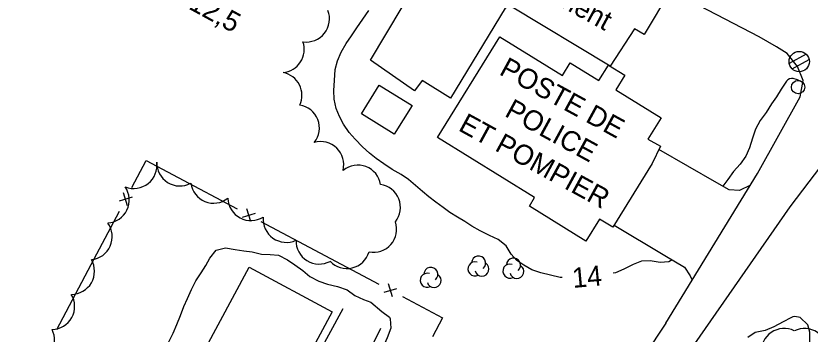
# Model space of a CAD drawing. Extents: x 219136 to 222520, y 5421589 to 5424530.
# Drawn here: x 220257.1 to 220376, y 5423476.2 to 5423523.8 of the extents above; entities that cross this region are included whole.
import ezdxf

# ---------------------------------------------------------------- set-up
doc = ezdxf.new("R2010")
doc.units = 0
for name, color, linetype in [('Level 19', 7, 'Continuous'), ('Level 2', 7, 'Continuous'), ('Level 21', 7, 'Continuous'), ('Level 3', 7, 'Continuous'), ('Level 31', 7, 'Continuous'), ('Level 36', 7, 'Continuous'), ('Level 37', 7, 'Continuous'), ('Level 44', 7, 'Continuous'), ('Level 52', 7, 'Continuous')]:
    doc.layers.add(name, color=color, linetype=linetype)

msp = doc.modelspace()

# ---------------------------------------------------------------- linework, layer by layer
at = {"layer": 'Level 19'}
for points in [[(220367.04, 5423498.43), (220367.03, 5423498.43), (220365.41, 5423497.65), (220363.86, 5423497.73), (220362.03, 5423498.78), (220353.34, 5423503.77)], [(220346.64, 5423492.48), (220354.22, 5423487.93), (220357.17, 5423486.18), (220358, 5423484.9), (220358.31, 5423484.23)], [(220309.62, 5423412.1), (220306.41, 5423416.08), (220301.31, 5423419.73), (220293.84, 5423424.22), (220279.64, 5423431.24), (220268.43, 5423436.55), (220263.02, 5423440.3), (220259.4, 5423443.91), (220257.3, 5423448.58), (220257.07, 5423453.25), (220257.68, 5423457.41), (220260.39, 5423461.45), (220264.09, 5423464.19), (220270.28, 5423466.47), (220275.2, 5423466.87), (220280.72, 5423465.24), (220293.76, 5423458.43), (220294.74, 5423459.24), (220306.07, 5423479.98)], [(220311.68, 5423476.99), (220299.86, 5423453.18), (220297.34, 5423445.49), (220296.32, 5423440.34), (220296.33, 5423435.83), (220297.41, 5423432.1), (220299.39, 5423429.1), (220302.74, 5423426.58), (220309.3, 5423424.23), (220314.56, 5423423.79), (220317.91, 5423424.63)]]:
    msp.add_lwpolyline(points, dxfattribs=at)
at = {"layer": 'Level 2'}
for points in [[(220319.96, 5423495.92), (220318.9, 5423496.7), (220317.93, 5423497.5), (220316.92, 5423498.4), (220315.87, 5423499.27), (220314.73, 5423500.02), (220313.39, 5423500.8), (220312.15, 5423501.63), (220311.03, 5423502.44), (220310.02, 5423503.23), (220308.98, 5423504.2), (220307.88, 5423505.31), (220306.95, 5423506.34), (220306.11, 5423507.57), (220305.51, 5423508.71), (220305.01, 5423509.93), (220304.71, 5423511.29), (220304.67, 5423512.6), (220304.77, 5423514.07), (220304.88, 5423515.75), (220305.23, 5423517.02), (220305.79, 5423518.35), (220306.51, 5423519.64), (220307.3, 5423520.79), (220308.09, 5423521.95), (220309, 5423523.28), (220309.91, 5423524.55)], [(220374.88, 5423513.78), (220374.1, 5423514.2), (220373.44, 5423514.38), (220373.19, 5423514.41), (220372.89, 5423514.35), (220372.62, 5423514.19), (220372.42, 5423514.01), (220371.66, 5423512.82), (220370.93, 5423511.65), (220370.18, 5423510.61), (220369.38, 5423509.31), (220368.48, 5423508.1), (220367.78, 5423506.84), (220367.36, 5423505.47), (220366.91, 5423504.04), (220366.33, 5423502.78), (220365.48, 5423501.6), (220364.5, 5423500.51), (220363.68, 5423499.31), (220362.92, 5423498.27)], [(220338.83, 5423484.63), (220338.56, 5423484.65), (220337.13, 5423484.97), (220335.65, 5423485.33), (220334.32, 5423485.76), (220333.1, 5423486.46), (220332.08, 5423487.18), (220331.24, 5423488.13), (220330.48, 5423489.38), (220329.26, 5423490.31), (220327.98, 5423490.92), (220326.59, 5423491.6), (220325.34, 5423492.33), (220324.26, 5423492.99), (220323.17, 5423493.64), (220322.05, 5423494.36), (220321.02, 5423495.11), (220319.96, 5423495.92)], [(220279.92, 5423474.92), (220280.6, 5423476.31), (220281.17, 5423477.63), (220281.69, 5423478.95), (220282.23, 5423480.31), (220282.75, 5423481.48), (220283.37, 5423482.84), (220284.03, 5423484.13), (220284.81, 5423485.35), (220285.5, 5423486.45), (220286.13, 5423487.54), (220287.07, 5423488.73), (220288.45, 5423489.05), (220289.91, 5423488.82), (220291.19, 5423488.62), (220292.44, 5423488.47), (220293.85, 5423488.15), (220295.15, 5423488.07), (220296.4, 5423487.98), (220297.74, 5423487.29), (220298.81, 5423486.52), (220300.03, 5423485.66), (220301.1, 5423484.79), (220302.43, 5423484.1), (220303.73, 5423483.63), (220305.23, 5423483.3), (220306.66, 5423482.78), (220307.83, 5423481.96), (220309.11, 5423481.33), (220310.19, 5423480.94), (220311.87, 5423479.57)], [(220355.34, 5423487.26), (220354.82, 5423487), (220353.51, 5423486.89), (220352.03, 5423487.12), (220350.73, 5423487.09), (220349.47, 5423486.6), (220348.11, 5423485.87), (220346.83, 5423485.36), (220346.47, 5423485.29)], [(220311.87, 5423479.57), (220312.98, 5423478.72), (220313.09, 5423478.48), (220313.22, 5423477.06), (220312.66, 5423475.64), (220312.06, 5423474.29), (220311.28, 5423472.93), (220310.45, 5423471.61), (220309.74, 5423470.38), (220309.14, 5423469.19), (220308.34, 5423467.91), (220307.56, 5423466.7), (220306.84, 5423465.5), (220305.99, 5423464.09), (220305.35, 5423462.69), (220304.58, 5423461.38), (220303.86, 5423460.04), (220303.28, 5423458.91), (220302.6, 5423457.73), (220301.9, 5423456.6), (220301.29, 5423455.39), (220300.38, 5423454.23)], [(220375.95, 5423475.02), (220375.91, 5423476.44), (220375.62, 5423477.54), (220374.48, 5423478.64), (220374.24, 5423478.72), (220373.65, 5423478.79), (220373.38, 5423478.74), (220373.11, 5423478.63), (220371.92, 5423478), (220370.56, 5423477.28), (220369.23, 5423476.69), (220367.75, 5423476.42), (220366.65, 5423475.68)]]:
    msp.add_lwpolyline(points, dxfattribs=at)
at = {"layer": 'Level 21'}
for points in [[(220354.35, 5423477.79), (220368.12, 5423500.19), (220374.47, 5423511.63), (220374.94, 5423514.08), (220374.08, 5423516.19), (220372.55, 5423518.11), (220370.93, 5423519.12), (220368.33, 5423520.62), (220355.57, 5423527.31)], [(220558.36, 5423407.54), (220559.08, 5423411.97), (220559.39, 5423415.96), (220558.61, 5423418.35), (220557.08, 5423420.09), (220555.08, 5423421.42), (220504.38, 5423448.27), (220439.72, 5423482.29), (220410.5, 5423497.92), (220389.28, 5423509.4), (220386.68, 5423509.92), (220385.06, 5423509.07), (220382.54, 5423507.19), (220379.41, 5423503.73), (220372.92, 5423495.21), (220358.67, 5423474.73)], [(220354.35, 5423477.79), (220344.96, 5423463.61), (220332.13, 5423445.06), (220318.17, 5423425.02), (220317.91, 5423424.63), (220307.64, 5423409.11), (220295.61, 5423391.04), (220289.8, 5423382.47), (220285.84, 5423375.17), (220282.22, 5423367.38), (220282.6, 5423358.53)]]:
    msp.add_lwpolyline(points, dxfattribs=at)
at = {"layer": 'Level 31'}
for points in [[(220320.2, 5423505.58), (220329.51, 5423520.64), (220338.88, 5423514.84), (220340.07, 5423516.76), (220344.35, 5423514.11), (220345.78, 5423516.41), (220348.24, 5423514.88), (220346.9, 5423512.72), (220353.67, 5423508.53), (220351.69, 5423505.33), (220353.58, 5423504.28), (220352.32, 5423501.66), (220346.44, 5423492.15), (220344.44, 5423493.38), (220342.4, 5423490.09), (220333.95, 5423495.32), (220334.73, 5423496.59)], [(220308.81, 5423509.09), (220311.48, 5423513.41), (220316.39, 5423510.37), (220313.72, 5423506.06)], [(220280.9, 5423465.61), (220291.97, 5423486.17), (220304.4, 5423479.48), (220300.47, 5423472.18), (220296.74, 5423474.19), (220289.6, 5423460.92)]]:
    msp.add_lwpolyline(points, close=True, dxfattribs=at)
at = {"layer": 'Level 36'}
for p, q in [((220375.37, 5423518.02), (220372.83, 5423516.62)), ((220373.29, 5423515.82), (220375.83, 5423517.22))]:
    msp.add_line(p, q, dxfattribs=at)
for centre, radius in [((220374.34, 5423516.92), 1.52), ((220374.17, 5423513.11), 1)]:
    msp.add_circle(centre, radius, dxfattribs=at)
at = {"layer": 'Level 37'}
for p, q in [((220273.79, 5423495.37), (220273.2, 5423497.29)), ((220274.46, 5423496.63), (220272.54, 5423496.04)), ((220292.26, 5423493.01), (220291.67, 5423494.93)), ((220291.01, 5423493.68), (220292.92, 5423494.26)), ((220312.21, 5423482.42), (220314.12, 5423483.01)), ((220313.46, 5423481.76), (220312.87, 5423483.67))]:
    msp.add_line(p, q, dxfattribs=at)
for points in [[(220274.43, 5423498.1), (220276.57, 5423502.14), (220281.37, 5423499.59)], [(220281.37, 5423499.59), (220290.2, 5423494.91)], [(220267.89, 5423485.72), (220272.57, 5423494.56)], [(220293.73, 5423493.03), (220302.57, 5423488.34)], [(220302.57, 5423488.34), (220311.4, 5423483.65)], [(220263.22, 5423476.88), (220267.89, 5423485.72)], [(220314.93, 5423481.78), (220320.94, 5423478.59), (220319.43, 5423475.77)]]:
    msp.add_lwpolyline(points, dxfattribs=at)
at = {"layer": 'Level 44'}
for centre, radius, start, end in [((220300.56, 5423523.31), 3.46, 261.4453, 21.4453), ((220296.78, 5423518.74), 3.46, 275.0469, 19.2467), ((220296.44, 5423511.88), 3.46, 335.0469, 79.2467), ((220299.05, 5423507), 3.46, 321.2293, 81.2293), ((220302.7, 5423501.5), 3.46, 345.9686, 105.9686), ((220274.73, 5423501.4), 3.46, 248.3788, 8.3788), ((220281.62, 5423501.78), 3.46, 177.9081, 297.9081), ((220308.26, 5423497.98), 3.46, 9.2931, 129.2931), ((220270.58, 5423496.24), 3.46, 274.0913, 34.0913), ((220286.67, 5423499.21), 3.46, 188.0701, 308.0701), ((220311.18, 5423495.11), 3.46, 321.7977, 81.7977), ((220292.26, 5423496.6), 3.46, 181.9922, 301.9922), ((220297.55, 5423493.35), 3.46, 174.8593, 294.8593), ((220268.03, 5423490.75), 3.46, 275.9748, 35.9748), ((220310.62, 5423491.86), 3.46, 258.6923, 18.6923), ((220302.47, 5423490.1), 3.46, 178.2709, 298.2709), ((220306.62, 5423489.44), 3.46, 223.5536, 343.5536), ((220326.35, 5423486.81), 1.05, 310.1588, 177.6158), ((220331.57, 5423486.48), 1.05, 310.1588, 177.6158), ((220265.38, 5423485.58), 3.46, 269.8838, 29.8838), ((220325.8, 5423485.92), 1.05, 72.005, 297.6935), ((220326.84, 5423485.88), 1.05, 194.8265, 57.5108), ((220331.02, 5423485.59), 1.05, 72.005, 297.6935), ((220332.06, 5423485.55), 1.05, 194.8265, 57.5108), ((220318.65, 5423484.22), 1.05, 72.005, 297.6935), ((220319.2, 5423485.11), 1.05, 310.1588, 177.6158), ((220319.69, 5423484.18), 1.05, 194.8265, 57.5108), ((220262.41, 5423480.32), 3.46, 271.1944, 31.1944), ((220259.4, 5423475.28), 3.46, 267.0823, 27.0823), ((220372.08, 5423473.56), 3.46, 63.8434, 183.8434), ((220375.12, 5423473.55), 3.46, 355.8208, 115.8208)]:
    msp.add_arc(centre, radius, start, end, dxfattribs=at)
at = {"layer": 'Level 52'}
msp.add_lwpolyline([(220355.07, 5423527.58), (220351.11, 5423520.96), (220349.68, 5423521.82), (220346.04, 5423516.24), (220331.11, 5423525.23), (220330.3, 5423524.93), (220322.15, 5423511.44), (220317.87, 5423514.09), (220316.74, 5423512.55), (220310.18, 5423517.11), (220326.67, 5423544.78)], dxfattribs=at)

# ---------------------------------------------------------------- texts
at = {"layer": 'Level 2'}
msp.add_text('14', height=3, rotation=5.2085, dxfattribs=at).set_placement((220340.48, 5423483.07))
at = {"layer": 'Level 3'}
msp.add_text('12,5', height=3, rotation=331.383, dxfattribs=at).set_placement((220282.78, 5423524.89))
at = {"layer": 'Level 31'}
for s, p in [('POSTE DE', (220329.28, 5423515.07)), ('POLICE', (220330.09, 5423508.84)), ('ET POMPIER', (220323.16, 5423506.7))]:
    msp.add_text(s, height=3, rotation=331.3547, dxfattribs=at).set_placement(p)
at = {"layer": 'Level 52'}
msp.add_text('Stationnement', height=3, rotation=331.383, dxfattribs=at).set_placement((220322.54, 5423533.88))

doc.saveas('drawing.dxf')
